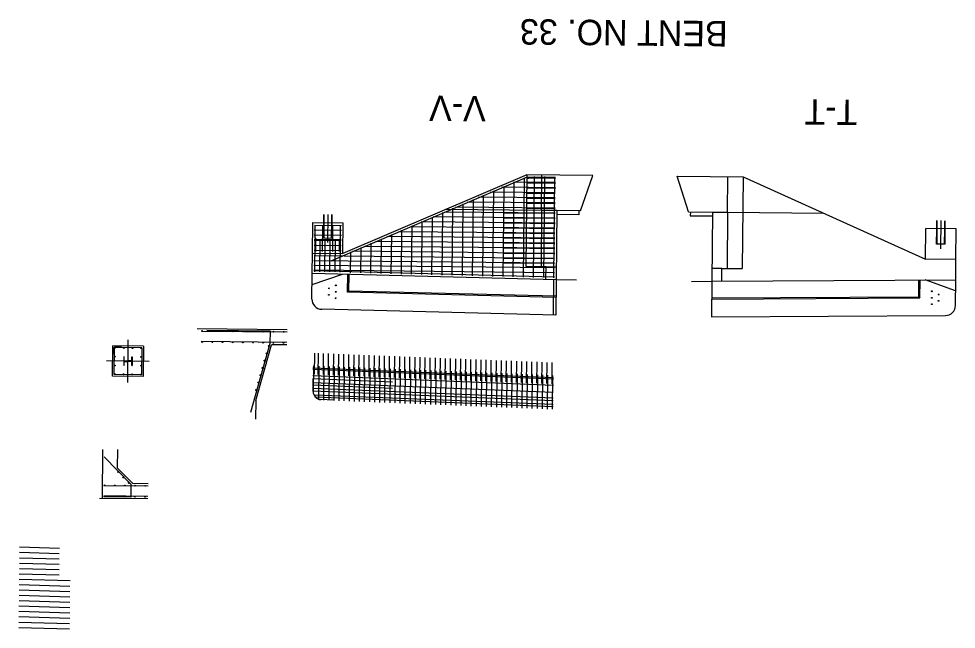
# Model space of a CAD drawing. Extents: x 631918 to 632319, y 373181 to 373282.
# Drawn here: x 632013.5 to 632105.7, y 373191.9 to 373251.9 of the extents above; entities that cross this region are included whole.
import ezdxf

# ---------------------------------------------------------------- set-up
doc = ezdxf.new("R2010")
doc.units = 0
for name, color, linetype in [('B_Boring', 7, 'Continuous'), ('BD-EXIST-OSB', 7, 'Continuous'), ('BD-LEGEND', 7, 'Continuous'), ('BD-PROP-COSS', 7, 'Continuous'), ('BD-REMOVE', 7, 'Continuous'), ('R_Border_Scale', 7, 'Continuous'), ('R_Road Edge of Travel', 7, 'Continuous'), ('R_Shade Removal', 7, 'Continuous'), ('R_Wall', 7, 'Continuous')]:
    doc.layers.add(name, color=color, linetype=linetype)

msp = doc.modelspace()

# ---------------------------------------------------------------- linework, layer by layer
at = {"layer": 'B_Boring'}
for p, q in [((632084.738, 373236.403), (632084.649, 373227.381)), ((632083.204, 373232.918), (632083.149, 373227.396)), ((632045.824, 373225.073), (632045.841, 373226.823)), ((632045.95, 373225.194), (632045.966, 373226.821)), ((632082.636, 373226.151), (632082.649, 373227.401)), ((632082.649, 373227.401), (632084.649, 373227.381)), ((632105.628, 373225.2), (632102.639, 373226.266)), ((632045.95, 373225.194), (632045.824, 373225.073)), ((632066.32, 373224.547), (632045.824, 373225.062)), ((632066.321, 373224.67), (632045.95, 373225.183))]:
    msp.add_line(p, q, dxfattribs=at)
at = {"layer": 'BD-EXIST-OSB'}
for p, q in [((632023.817, 373218.717), (632023.809, 373217.863)), ((632023.864, 373218.716), (632023.817, 373218.717)), ((632023.86, 373218.313), (632023.864, 373218.716)), ((632024.6, 373218.305), (632024.604, 373218.709)), ((632024.604, 373218.709), (632024.651, 373218.709)), ((632024.651, 373218.709), (632024.642, 373217.854)), ((632023.856, 373217.862), (632023.809, 373217.863)), ((632023.856, 373217.862), (632023.86, 373218.266)), ((632023.86, 373218.313), (632024.23, 373218.309)), ((632023.86, 373218.266), (632024.229, 373218.262)), ((632024.599, 373218.259), (632024.229, 373218.262)), ((632024.6, 373218.305), (632024.23, 373218.309)), ((632024.595, 373217.855), (632024.599, 373218.259)), ((632024.595, 373217.855), (632024.642, 373217.854))]:
    msp.add_line(p, q, dxfattribs=at)
at = {"layer": 'BD-LEGEND'}
for p, q in [((632039.871, 373221.38), (632031.026, 373221.468)), ((632022.715, 373216.801), (632022.745, 373219.801)), ((632025.744, 373219.771), (632022.745, 373219.801)), ((632025.744, 373219.771), (632025.715, 373216.771)), ((632036.79, 373214.411), (632038.345, 373219.895)), ((632039.856, 373219.88), (632038.345, 373219.895)), ((632025.715, 373216.771), (632022.715, 373216.801)), ((632036.79, 373214.411), (632036.772, 373212.58)), ((632021.723, 373209.619), (632021.675, 373204.789)), ((632023.205, 373207.774), (632023.223, 373209.604)), ((632023.205, 373207.774), (632024.69, 373206.259)), ((632026.201, 373206.244), (632024.69, 373206.259)), ((632026.187, 373204.744), (632021.422, 373204.791))]:
    msp.add_line(p, q, dxfattribs=at)
at = {"layer": 'BD-PROP-COSS'}
for p, q in [((632063.49, 373236.364), (632044.181, 373228.106)), ((632063.187, 373236.325), (632063.089, 373226.547)), ((632066.27, 373236.336), (632063.49, 373236.364)), ((632066.269, 373236.253), (632063.52, 373236.28)), ((632063.52, 373236.28), (632063.603, 373236.279)), ((632064.188, 373236.44), (632064.089, 373226.506)), ((632065.188, 373236.43), (632065.089, 373226.496)), ((632066.188, 373236.42), (632066.089, 373226.486)), ((632066.26, 373235.336), (632060.997, 373235.389)), ((632061.178, 373235.466), (632061.09, 373226.598)), ((632062.182, 373235.895), (632062.09, 373226.573)), ((632066.265, 373235.836), (632062.14, 373235.877)), ((632066.259, 373235.253), (632063.51, 373235.28)), ((632066.264, 373235.753), (632063.515, 373235.78)), ((632066.25, 373234.336), (632058.712, 373234.411)), ((632059.169, 373234.607), (632059.09, 373226.65)), ((632066.255, 373234.836), (632059.855, 373234.9)), ((632060.174, 373235.036), (632060.09, 373226.624)), ((632066.249, 373234.253), (632063.5, 373234.28)), ((632066.254, 373234.753), (632063.505, 373234.78)), ((632056.156, 373233.318), (632056.091, 373226.727)), ((632066.24, 373233.336), (632056.427, 373233.434)), ((632057.161, 373233.748), (632057.091, 373226.701)), ((632066.245, 373233.836), (632057.57, 373233.923)), ((632058.165, 373234.177), (632058.09, 373226.675)), ((632066.24, 373233.253), (632063.49, 373233.28)), ((632066.245, 373233.753), (632063.495, 373233.78)), ((632054.148, 373232.459), (632054.091, 373226.778)), ((632054.242, 373232.499), (632066.231, 373232.38)), ((632055.152, 373232.889), (632055.091, 373226.752)), ((632055.371, 373232.982), (632066.236, 373232.874)), ((632066.235, 373232.791), (632061.235, 373232.841)), ((632045.222, 373231.593), (632042.555, 373231.619)), ((632042.626, 373230.368), (632042.639, 373231.66)), ((632043.363, 373229.069), (632043.389, 373231.652)), ((632044.363, 373229.059), (632044.389, 373231.642)), ((632045.126, 373230.343), (632045.139, 373231.635)), ((632051.982, 373231.533), (632066.221, 373231.391)), ((632052.139, 373231.6), (632052.092, 373226.829)), ((632053.143, 373232.03), (632053.091, 373226.804)), ((632053.112, 373232.016), (632066.226, 373231.886)), ((632066.225, 373231.802), (632061.225, 373231.852)), ((632066.23, 373232.297), (632061.23, 373232.346)), ((632045.212, 373230.634), (632042.546, 373230.661)), ((632045.217, 373231.134), (632042.551, 373231.161)), ((632049.723, 373230.567), (632066.211, 373230.403)), ((632050.13, 373230.741), (632050.092, 373226.881)), ((632050.853, 373231.05), (632066.216, 373230.897)), ((632051.135, 373231.17), (632051.092, 373226.855)), ((632066.215, 373230.814), (632061.216, 373230.863)), ((632066.22, 373231.308), (632061.22, 373231.358)), ((632045.203, 373229.634), (632042.536, 373229.661)), ((632045.208, 373230.134), (632042.541, 373230.161)), ((632045.208, 373230.218), (632042.542, 373230.244)), ((632042.594, 373227.077), (632042.626, 373230.285)), ((632042.626, 373230.368), (632042.709, 373230.284)), ((632042.697, 373229.076), (632042.709, 373230.284)), ((632043.094, 373227.072), (632043.126, 373230.28)), ((632043.594, 373227.067), (632043.625, 373230.275)), ((632044.094, 373227.062), (632044.125, 373230.27)), ((632044.594, 373227.057), (632044.625, 373230.265)), ((632045.03, 373229.053), (632045.042, 373230.261)), ((632045.126, 373230.343), (632045.042, 373230.261)), ((632045.094, 373227.052), (632045.125, 373230.26)), ((632047.464, 373229.6), (632066.201, 373229.414)), ((632048.122, 373229.882), (632048.092, 373226.932)), ((632048.594, 373230.084), (632066.206, 373229.908)), ((632049.126, 373230.311), (632049.092, 373226.906)), ((632066.205, 373229.825), (632061.206, 373229.875)), ((632066.21, 373230.319), (632061.211, 373230.369)), ((632045.198, 373229.134), (632042.531, 373229.161)), ((632046.113, 373229.023), (632046.093, 373226.983)), ((632046.334, 373229.117), (632066.196, 373228.92)), ((632047.117, 373229.452), (632047.093, 373226.957)), ((632066.196, 373228.837), (632061.196, 373228.886)), ((632066.201, 373229.331), (632061.201, 373229.381)), ((632042.521, 373228.192), (632066.187, 373227.957)), ((632042.526, 373228.661), (632066.192, 373228.426)), ((632066.186, 373227.874), (632061.186, 373227.923)), ((632066.191, 373228.342), (632061.191, 373228.392)), ((632066.173, 373226.551), (632042.511, 373227.158)), ((632042.512, 373227.255), (632066.178, 373227.019)), ((632042.517, 373227.723), (632066.182, 373227.488)), ((632038.231, 373221.23), (632031.981, 373221.292)), ((632039.869, 373221.13), (632031.451, 373221.214)), ((632038.219, 373220.063), (632038.231, 373221.23)), ((632022.861, 373218.966), (632022.868, 373219.633)), ((632025.576, 373219.606), (632022.868, 373219.633)), ((632022.883, 373216.966), (632022.91, 373219.674)), ((632023.577, 373219.667), (632022.91, 373219.674)), ((632025.576, 373219.606), (632025.55, 373216.939)), ((632039.859, 373220.13), (632031.441, 373220.214)), ((632036.297, 373213.282), (632038.219, 373220.063)), ((632042.577, 373216.994), (632042.597, 373219.077)), ((632042.931, 373219.064), (632042.91, 373216.98)), ((632043.43, 373219.044), (632043.41, 373216.96)), ((632043.93, 373219.024), (632043.91, 373216.94)), ((632044.43, 373219.004), (632044.409, 373216.921)), ((632044.93, 373218.984), (632044.909, 373216.901)), ((632045.43, 373218.964), (632045.409, 373216.881)), ((632045.93, 373218.944), (632045.909, 373216.861)), ((632046.429, 373218.924), (632046.409, 373216.841)), ((632046.929, 373218.904), (632046.909, 373216.821)), ((632047.429, 373218.884), (632047.408, 373216.801)), ((632047.929, 373218.864), (632047.908, 373216.781)), ((632048.429, 373218.844), (632048.408, 373216.761)), ((632048.929, 373218.824), (632048.908, 373216.741)), ((632049.428, 373218.804), (632049.408, 373216.721)), ((632049.928, 373218.784), (632049.908, 373216.701)), ((632050.428, 373218.764), (632050.407, 373216.681)), ((632050.928, 373218.744), (632050.907, 373216.661)), ((632051.428, 373218.724), (632051.407, 373216.641)), ((632051.928, 373218.704), (632051.907, 373216.621)), ((632052.427, 373218.684), (632052.407, 373216.601)), ((632052.927, 373218.664), (632052.906, 373216.581)), ((632053.427, 373218.644), (632053.406, 373216.561)), ((632053.927, 373218.624), (632053.906, 373216.541)), ((632054.427, 373218.604), (632054.406, 373216.521)), ((632054.926, 373218.584), (632054.906, 373216.501)), ((632055.426, 373218.564), (632055.406, 373216.481)), ((632055.926, 373218.544), (632055.905, 373216.461)), ((632056.426, 373218.524), (632056.405, 373216.441)), ((632042.476, 373215.247), (632042.502, 373217.83)), ((632043.002, 373217.81), (632042.969, 373214.561)), ((632043.501, 373217.79), (632043.468, 373214.457)), ((632044.001, 373217.77), (632043.968, 373214.437)), ((632044.501, 373217.75), (632044.468, 373214.417)), ((632045.001, 373217.731), (632044.968, 373214.397)), ((632045.501, 373217.711), (632045.468, 373214.377)), ((632046, 373217.691), (632045.967, 373214.357)), ((632046.5, 373217.671), (632046.467, 373214.337)), ((632047, 373217.651), (632046.967, 373214.317)), ((632047.5, 373217.631), (632047.467, 373214.297)), ((632048, 373217.611), (632047.967, 373214.278)), ((632056.926, 373218.504), (632056.905, 373216.421)), ((632057.426, 373218.485), (632057.405, 373216.401)), ((632057.925, 373218.465), (632057.905, 373216.381)), ((632058.425, 373218.445), (632058.405, 373216.361)), ((632058.925, 373218.425), (632058.904, 373216.341)), ((632059.425, 373218.405), (632059.404, 373216.321)), ((632059.925, 373218.385), (632059.904, 373216.301)), ((632060.425, 373218.365), (632060.404, 373216.281)), ((632060.924, 373218.345), (632060.904, 373216.262)), ((632061.424, 373218.325), (632061.404, 373216.242)), ((632061.924, 373218.305), (632061.903, 373216.222)), ((632062.424, 373218.285), (632062.403, 373216.202)), ((632062.924, 373218.265), (632062.903, 373216.182)), ((632063.424, 373218.245), (632063.403, 373216.162)), ((632063.923, 373218.225), (632063.903, 373216.142)), ((632064.423, 373218.205), (632064.402, 373216.122)), ((632064.923, 373218.185), (632064.902, 373216.102)), ((632065.423, 373218.165), (632065.402, 373216.082)), ((632065.923, 373218.145), (632065.902, 373216.062)), ((632025.55, 373216.939), (632022.883, 373216.966)), ((632066.067, 373215.888), (632042.408, 373216.834)), ((632066.073, 373216.513), (632042.415, 373217.459)), ((632066.074, 373216.638), (632042.416, 373217.584)), ((632048.5, 373217.591), (632048.466, 373214.258)), ((632048.999, 373217.571), (632048.966, 373214.238)), ((632049.499, 373217.551), (632049.466, 373214.218)), ((632049.999, 373217.531), (632049.966, 373214.198)), ((632050.499, 373217.511), (632050.466, 373214.178)), ((632050.999, 373217.491), (632050.966, 373214.158)), ((632051.499, 373217.471), (632051.465, 373214.138)), ((632051.998, 373217.451), (632051.965, 373214.118)), ((632052.498, 373217.431), (632052.465, 373214.098)), ((632052.998, 373217.411), (632052.965, 373214.078)), ((632053.498, 373217.391), (632053.465, 373214.058)), ((632053.998, 373217.371), (632053.965, 373214.038)), ((632054.498, 373217.351), (632054.464, 373214.018)), ((632054.997, 373217.331), (632054.964, 373213.998)), ((632055.497, 373217.311), (632055.464, 373213.978)), ((632055.997, 373217.291), (632055.964, 373213.958)), ((632056.497, 373217.271), (632056.464, 373213.938)), ((632056.997, 373217.251), (632056.964, 373213.918)), ((632057.497, 373217.231), (632057.463, 373213.898)), ((632057.996, 373217.211), (632057.963, 373213.878)), ((632058.496, 373217.191), (632058.463, 373213.858)), ((632058.996, 373217.171), (632058.963, 373213.838)), ((632059.496, 373217.151), (632059.463, 373213.818)), ((632059.996, 373217.131), (632059.962, 373213.798)), ((632060.495, 373217.111), (632060.462, 373213.778)), ((632060.995, 373217.091), (632060.962, 373213.758)), ((632061.495, 373217.072), (632061.462, 373213.738)), ((632061.995, 373217.052), (632061.962, 373213.718)), ((632062.495, 373217.032), (632062.462, 373213.698)), ((632062.995, 373217.012), (632062.961, 373213.678)), ((632063.494, 373216.992), (632063.461, 373213.658)), ((632063.994, 373216.972), (632063.961, 373213.638)), ((632064.494, 373216.952), (632064.461, 373213.619)), ((632064.994, 373216.932), (632064.961, 373213.599)), ((632065.494, 373216.912), (632065.461, 373213.579)), ((632065.994, 373216.892), (632065.96, 373213.559)), ((632050.23, 373215.604), (632042.399, 373215.917)), ((632066.06, 373215.222), (632042.402, 373216.167)), ((632050.236, 373216.229), (632042.406, 373216.542)), ((632042.435, 373215.309), (632042.447, 373216.559)), ((632066.052, 373214.389), (632042.394, 373215.334)), ((632066.054, 373214.639), (632042.396, 373215.584)), ((632066.048, 373214.014), (632042.617, 373214.95)), ((632066.046, 373213.805), (632042.609, 373214.742)), ((632044.444, 373214.46), (632043.195, 373214.51)), ((632021.882, 373208.884), (632024.522, 373206.191)), ((632026.199, 373205.994), (632021.854, 373206.037)), ((632024.522, 373206.191), (632024.51, 373204.927)), ((632024.51, 373204.927), (632021.843, 373204.954)), ((632026.189, 373204.994), (632021.844, 373205.037)), ((632017.474, 373199.346), (632013.559, 373199.463)), ((632017.48, 373199.873), (632013.565, 373199.991)), ((632017.464, 373198.292), (632013.549, 373198.409)), ((632017.469, 373198.819), (632013.554, 373198.936)), ((632017.451, 373197.237), (632013.536, 373197.355)), ((632017.459, 373197.765), (632013.544, 373197.882)), ((632018.528, 373196.678), (632013.531, 373196.828)), ((632018.518, 373195.624), (632013.52, 373195.773)), ((632018.523, 373196.151), (632013.525, 373196.3)), ((632018.508, 373194.569), (632013.51, 373194.719)), ((632018.513, 373195.096), (632013.515, 373195.246)), ((632018.497, 373193.515), (632013.499, 373193.664)), ((632018.502, 373194.042), (632013.505, 373194.192)), ((632018.492, 373192.988), (632013.494, 373193.137)), ((632018.481, 373191.933), (632013.484, 373192.083)), ((632018.487, 373192.46), (632013.489, 373192.61))]:
    msp.add_line(p, q, dxfattribs=at)
for centre, radius in [((632031.535, 373221.255), 0.0417), ((632032.535, 373221.245), 0.0417), ((632033.535, 373221.235), 0.0417), ((632034.535, 373221.225), 0.0417), ((632035.535, 373221.215), 0.0417), ((632036.535, 373221.205), 0.0417), ((632037.535, 373221.195), 0.0417), ((632038.535, 373221.185), 0.0417), ((632039.535, 373221.175), 0.0417), ((632022.951, 373219.59), 0.0417), ((632023.812, 373219.582), 0.0417), ((632024.673, 373219.573), 0.0417), ((632025.534, 373219.564), 0.0417), ((632031.524, 373220.172), 0.0417), ((632032.524, 373220.162), 0.0417), ((632033.524, 373220.152), 0.0417), ((632034.524, 373220.142), 0.0417), ((632035.524, 373220.132), 0.0417), ((632036.524, 373220.122), 0.0417), ((632037.524, 373220.112), 0.0417), ((632038.078, 373219.771), 0.0556), ((632038.524, 373220.102), 0.0417), ((632039.524, 373220.092), 0.0417), ((632022.942, 373218.729), 0.0417), ((632025.526, 373218.703), 0.0417), ((632037.875, 373219.052), 0.0556), ((632022.934, 373217.868), 0.0417), ((632025.517, 373217.842), 0.0417), ((632037.467, 373217.613), 0.0556), ((632037.671, 373218.333), 0.0556), ((632022.925, 373217.007), 0.0417), ((632023.786, 373216.998), 0.0417), ((632024.647, 373216.99), 0.0417), ((632025.508, 373216.981), 0.0417), ((632037.263, 373216.894), 0.0556), ((632037.059, 373216.174), 0.0556), ((632036.855, 373215.455), 0.0556), ((632023.253, 373207.407), 0.0556), ((632023.785, 373206.864), 0.0556), ((632021.923, 373206.078), 0.0417), ((632022.923, 373206.068), 0.0417), ((632023.923, 373206.058), 0.0417), ((632024.317, 373206.322), 0.0556), ((632024.923, 373206.048), 0.0417), ((632025.923, 373206.038), 0.0417), ((632021.912, 373204.995), 0.0417), ((632022.912, 373204.985), 0.0417), ((632023.912, 373204.975), 0.0417), ((632024.912, 373204.965), 0.0417), ((632025.912, 373204.955), 0.0417)]:
    msp.add_circle(centre, radius, dxfattribs=at)
msp.add_arc((632043.227, 373215.301), 0.792, 179.43036, 267.712, dxfattribs=at)
at = {"layer": 'R_Border_Scale'}
for p, q in [((632064.905, 373233.1), (632064.939, 373236.599)), ((632083.204, 373232.918), (632083.239, 373236.418)), ((632064.905, 373233.1), (632055.442, 373233.194)), ((632066.405, 373233.085), (632064.905, 373233.1)), ((632081.704, 373232.933), (632083.204, 373232.918)), ((632083.204, 373232.918), (632092.667, 373232.824)), ((632066.337, 373226.297), (632042.342, 373226.913)), ((632065.35, 373227.573), (632066.35, 373227.563)), ((632082.649, 373227.401), (632081.649, 373227.411)), ((632081.636, 373226.145), (632105.639, 373226.283))]:
    msp.add_line(p, q, dxfattribs=at)
at = {"layer": 'R_Road Edge of Travel'}
for p, q in [((632043.475, 373231.902), (632043.483, 373232.705)), ((632043.522, 373231.901), (632043.53, 373232.705)), ((632044.261, 373231.894), (632044.269, 373232.697)), ((632044.308, 373231.893), (632044.316, 373232.697)), ((632043.46, 373230.402), (632043.475, 373231.902)), ((632043.507, 373230.401), (632043.522, 373231.901)), ((632044.246, 373230.394), (632044.261, 373231.894)), ((632044.293, 373230.393), (632044.308, 373231.893)), ((632103.772, 373231.302), (632103.78, 373232.106)), ((632103.819, 373231.302), (632103.827, 373232.105)), ((632104.558, 373231.294), (632104.566, 373232.098)), ((632104.605, 373231.294), (632104.613, 373232.097)), ((632103.757, 373229.802), (632103.772, 373231.302)), ((632103.804, 373229.802), (632103.819, 373231.302)), ((632104.544, 373229.794), (632104.558, 373231.294)), ((632104.59, 373229.794), (632104.605, 373231.294)), ((632043.46, 373230.402), (632044.293, 373230.393)), ((632104.59, 373229.794), (632103.757, 373229.802))]:
    msp.add_line(p, q, dxfattribs=at)
at = {"layer": 'R_Shade Removal'}
for p, q in [((632063.439, 373236.614), (632045.362, 373228.883)), ((632063.439, 373236.614), (632063.35, 373227.593)), ((632069.939, 373236.55), (632063.439, 373236.614)), ((632068.738, 373233.062), (632069.939, 373236.55)), ((632078.239, 373236.467), (632084.738, 373236.403)), ((632079.371, 373232.956), (632078.239, 373236.467)), ((632084.738, 373236.403), (632102.659, 373228.313)), ((632064.905, 373233.1), (632064.85, 373227.578)), ((632066.405, 373233.085), (632066.337, 373226.297)), ((632068.567, 373232.688), (632066.401, 373232.71)), ((632068.738, 373233.062), (632066.405, 373233.085)), ((632068.571, 373233.063), (632068.567, 373232.688)), ((632079.371, 373232.956), (632081.704, 373232.933)), ((632079.537, 373232.954), (632079.534, 373232.579)), ((632079.534, 373232.579), (632081.7, 373232.558)), ((632081.704, 373232.933), (632081.636, 373226.145)), ((632042.362, 373228.913), (632042.392, 373231.912)), ((632042.392, 373231.912), (632045.392, 373231.883)), ((632045.362, 373228.883), (632045.392, 373231.883)), ((632102.659, 373228.313), (632102.689, 373231.313)), ((632105.689, 373231.283), (632102.689, 373231.313)), ((632105.659, 373228.283), (632105.689, 373231.283)), ((632042.342, 373226.913), (632042.362, 373228.913)), ((632042.362, 373228.913), (632045.362, 373228.883)), ((632105.659, 373228.283), (632102.659, 373228.313)), ((632105.639, 373226.283), (632105.659, 373228.283)), ((632042.317, 373224.397), (632042.342, 373226.913)), ((632042.331, 373225.829), (632045.341, 373226.836)), ((632065.35, 373227.573), (632063.35, 373227.593)), ((632065.337, 373226.323), (632065.35, 373227.573)), ((632066.087, 373226.3), (632066.052, 373222.8)), ((632066.337, 373226.297), (632066.302, 373222.797)), ((632068.336, 373226.246), (632066.337, 373226.297)), ((632079.636, 373226.134), (632081.636, 373226.145)), ((632081.636, 373226.145), (632081.602, 373222.645)), ((632101.997, 373224.636), (632102.014, 373226.264)), ((632102.121, 373224.513), (632102.139, 373226.263)), ((632105.614, 373223.768), (632105.639, 373226.283)), ((632081.619, 373224.395), (632102.121, 373224.503)), ((632081.62, 373224.518), (632101.997, 373224.626)), ((632101.997, 373224.636), (632102.121, 373224.513)), ((632066.302, 373222.797), (632043.291, 373223.388)), ((632081.602, 373222.645), (632104.62, 373222.778))]:
    msp.add_line(p, q, dxfattribs=at)
for centre in [(632043.994, 373225.444), (632044.657, 373225.103), (632044.664, 373225.738), (632103.294, 373225.156), (632043.988, 373224.808), (632044.651, 373224.467), (632103.288, 373224.52), (632103.952, 373224.212), (632103.958, 373224.847), (632103.282, 373223.884)]:
    msp.add_circle(centre, 0.0417, dxfattribs=at)
for centre, start, end in [((632043.317, 373224.387), 179.43036, 268.53089), ((632104.614, 373223.778), 270.32983, 359.43036)]:
    msp.add_arc(centre, 1, start, end, dxfattribs=at)
at = {"layer": 'R_Wall'}
for p, q in [((632043.872, 373229.938), (632043.9, 373232.701)), ((632104.169, 373229.338), (632104.197, 373232.101)), ((632024.209, 373216.2), (632024.251, 373220.4)), ((632026.316, 373218.265), (632022.116, 373218.307))]:
    msp.add_line(p, q, dxfattribs=at)

# ---------------------------------------------------------------- texts
at = {"layer": 'BD-REMOVE'}
for s, p in [('BENT NO. 33', (632083.22, 373251.714)), ('V-V', (632059.435, 373244.358)), ('T-T', (632095.976, 373243.995))]:
    msp.add_text(s, height=2.5, rotation=179.43036, dxfattribs=at).set_placement(p)

doc.saveas('drawing.dxf')
